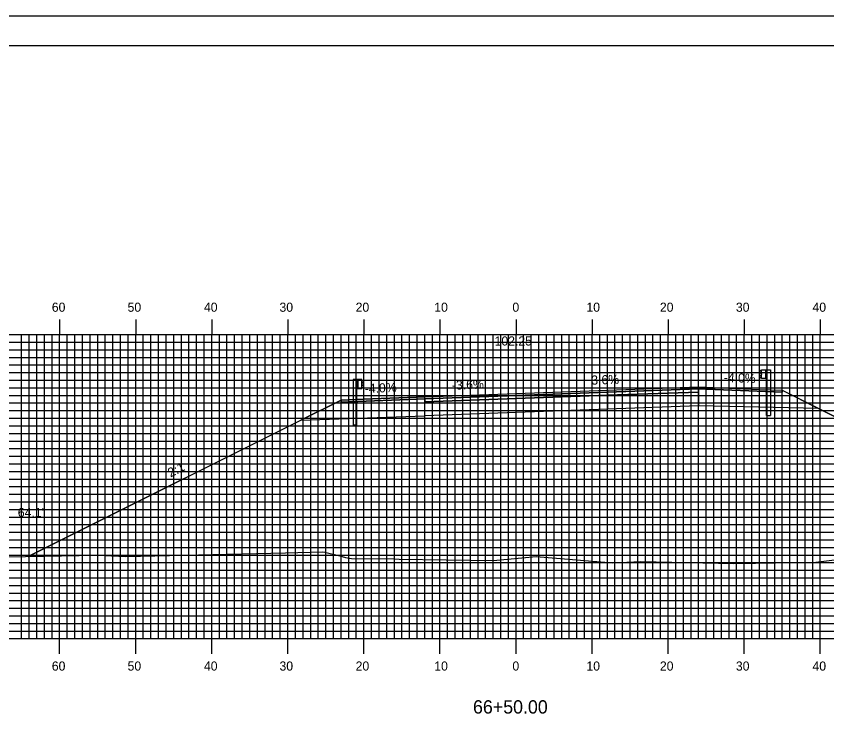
# Model space of a CAD drawing. Extents: x 1759036 to 1759380, y 442591 to 442811.
# Drawn here: x 1759136.4 to 1759243, y 442716.9 to 442810.5 of the extents above; entities that cross this region are included whole.
import ezdxf

# ---------------------------------------------------------------- set-up
doc = ezdxf.new("R2010")
doc.units = 0
for name, color, linetype in [('ANNOTATION', 7, 'Continuous'), ('BORDER', 7, 'Continuous'), ('D_Guardrail_Beam_Lt', 7, 'Continuous'), ('D_Guardrail_Beam_Rt', 7, 'Continuous'), ('D_Roadway_Centerline', 7, 'Continuous'), ('D_Roadway_Centerline_Text', 7, 'Continuous'), ('D_Roadway_Edge_Shoulder', 7, 'Continuous'), ('D_Roadway_Edge_TW', 7, 'Continuous'), ('D_Roadway_Pavement', 7, 'Continuous'), ('D_Roadway_SlopeLines', 7, 'Continuous'), ('D_Roadway_SubGrade', 7, 'Continuous'), ('D_Text_Standard', 7, 'Continuous'), ('H_V ANNOTATION', 7, 'Continuous'), ('MAJOR', 7, 'Continuous'), ('MINOR', 7, 'Continuous'), ('PLOT BOUNDARY', 7, 'Continuous'), ('S_Roadway_Centerline', 7, 'Continuous')]:
    doc.layers.add(name, color=color, linetype=linetype)

msp = doc.modelspace()

# ---------------------------------------------------------------- linework, layer by layer
at = {"layer": 'BORDER'}
msp.add_lwpolyline([(1759052.56, 442596.67), (1759372.56, 442596.67), (1759372.56, 442806.67), (1759052.56, 442806.67)], close=True, dxfattribs=at)
at = {"layer": 'D_Guardrail_Beam_Lt'}
for p, q in [((1759180.73, 442762.75), (1759180.73, 442756.75)), ((1759181.2, 442762.75), (1759180.73, 442762.75)), ((1759181.89, 442762.75), (1759181.2, 442762.75)), ((1759181.2, 442762.75), (1759181.2, 442761.58)), ((1759181.27, 442762.75), (1759181.27, 442761.58)), ((1759181.37, 442762.75), (1759181.37, 442761.58)), ((1759181.89, 442761.58), (1759181.89, 442762.75)), ((1759181.89, 442762.66), (1759181.96, 442762.65)), ((1759181.9, 442762.2), (1759181.9, 442762.13)), ((1759182.12, 442762.4), (1759181.93, 442762.26)), ((1759181.93, 442762.06), (1759182.12, 442761.93)), ((1759181.98, 442762.64), (1759182.12, 442762.54)), ((1759181.2, 442761.58), (1759181.89, 442761.58)), ((1759181.22, 442756.75), (1759181.22, 442761.58)), ((1759181.96, 442761.68), (1759181.89, 442761.66)), ((1759182.12, 442761.78), (1759181.98, 442761.68)), ((1759181.22, 442756.75), (1759180.73, 442756.75))]:
    msp.add_line(p, q, dxfattribs=at)
for centre, major_axis, start_param, end_param in [((1759181.97, 442762.2), (-0.0789, 0), 5.323254, 6.283185), ((1759181.97, 442762.13), (-0.0789, 0), 6.283185, 7.243116), ((1759181.96, 442762.61), (0.0417, 0), 0.959931, 1.376053), ((1759182.07, 442762.47), (0.0877, 0), 5.323254, 7.243116), ((1759182.07, 442761.86), (0.0877, 0), 5.323254, 7.243116), ((1759181.96, 442761.72), (0.0417, 0), 4.907132, 5.323254)]:
    msp.add_ellipse(centre, major_axis=major_axis, ratio=0.995501, start_param=start_param, end_param=end_param, dxfattribs=at)
at = {"layer": 'D_Guardrail_Beam_Rt'}
for p, q in [((1759234.43, 442764.04), (1759235.12, 442764.04)), ((1759234.43, 442762.88), (1759234.43, 442764.04)), ((1759234.95, 442764.04), (1759234.95, 442762.88)), ((1759235.06, 442764.04), (1759235.06, 442762.88)), ((1759235.12, 442764.04), (1759235.59, 442764.04)), ((1759235.12, 442764.04), (1759235.12, 442762.88)), ((1759235.59, 442764.04), (1759235.59, 442758.04)), ((1759234.34, 442763.94), (1759234.2, 442763.84)), ((1759234.2, 442763.69), (1759234.39, 442763.56)), ((1759234.39, 442763.36), (1759234.2, 442763.22)), ((1759234.2, 442763.08), (1759234.34, 442762.98)), ((1759234.43, 442763.96), (1759234.36, 442763.94)), ((1759234.36, 442762.97), (1759234.43, 442762.96)), ((1759234.43, 442763.49), (1759234.43, 442763.42)), ((1759235.12, 442762.88), (1759234.43, 442762.88)), ((1759235.1, 442758.04), (1759235.1, 442762.88)), ((1759235.1, 442758.04), (1759235.59, 442758.04))]:
    msp.add_line(p, q, dxfattribs=at)
for centre, major_axis, start_param, end_param in [((1759234.25, 442763.77), (-0.0877, 0), 5.323254, 7.243116), ((1759234.25, 442763.15), (-0.0877, 0), 5.323254, 7.243116), ((1759234.37, 442763.9), (-0.0417, 0), 4.907132, 5.323254), ((1759234.37, 442763.01), (-0.0417, 0), 0.959931, 1.376053), ((1759234.35, 442763.49), (0.0789, 0), 0, 0.959931), ((1759234.35, 442763.42), (0.0789, 0), 5.323254, 6.283185)]:
    msp.add_ellipse(centre, major_axis=major_axis, ratio=0.995501, start_param=start_param, end_param=end_param, dxfattribs=at)
at = {"layer": 'D_Roadway_Centerline'}
msp.add_lwpolyline([(1759138.03, 442739.48), (1759173.87, 442757.4), (1759179.16, 442760.04), (1759182.16, 442760.16), (1759190.16, 442760.48), (1759202.16, 442760.91), (1759214.16, 442761.35), (1759226.16, 442761.78), (1759234.16, 442761.46), (1759237.16, 442761.34), (1759241.91, 442758.96), (1759280.16, 442739.84)], dxfattribs=at)
at = {"layer": 'D_Roadway_Edge_Shoulder'}
for points in [[(1759226.16, 442761.78), (1759234.16, 442761.46), (1759234.16, 442761.46), (1759237.16, 442761.34), (1759237.16, 442761.09), (1759226.16, 442761.53)], [(1759190.16, 442760.48), (1759182.16, 442760.16), (1759182.16, 442760.16), (1759179.16, 442760.04), (1759179.16, 442759.79), (1759190.16, 442760.23)]]:
    msp.add_lwpolyline(points, close=True, dxfattribs=at)
at = {"layer": 'D_Roadway_Edge_TW'}
for points in [[(1759190.16, 442760.23), (1759190.16, 442760.48), (1759202.16, 442760.91), (1759214.16, 442761.35), (1759214.16, 442761.1), (1759202.16, 442760.66)], [(1759214.16, 442761.35), (1759226.16, 442761.78), (1759226.16, 442761.53), (1759214.16, 442761.1)]]:
    msp.add_lwpolyline(points, close=True, dxfattribs=at)
at = {"layer": 'D_Roadway_Pavement'}
for points in [[(1759190.16, 442759.82), (1759190.16, 442760.23), (1759202.16, 442760.66), (1759214.16, 442761.1), (1759214.16, 442760.68), (1759202.16, 442760.25)], [(1759214.16, 442761.1), (1759226.16, 442761.53), (1759226.16, 442761.11), (1759214.16, 442760.68)]]:
    msp.add_lwpolyline(points, close=True, dxfattribs=at)
for points in [[(1759226.16, 442761.53), (1759226.16, 442761.11)], [(1759226.16, 442761.53), (1759226.16, 442761.11)], [(1759190.16, 442760.23), (1759190.16, 442759.82)]]:
    msp.add_lwpolyline(points, dxfattribs=at)
at = {"layer": 'D_Roadway_SlopeLines'}
for points in [[(1759237.16, 442761.34), (1759280.16, 442739.84)], [(1759179.16, 442760.04), (1759138.03, 442739.48)]]:
    msp.add_lwpolyline(points, dxfattribs=at)
at = {"layer": 'D_Roadway_SubGrade'}
for points in [[(1759214.16, 442760.68), (1759226.16, 442761.11), (1759226.16, 442759.28), (1759214.16, 442758.85)], [(1759226.16, 442761.11), (1759226.16, 442761.53), (1759237.16, 442761.09), (1759237.16, 442761.34), (1759241.91, 442758.96), (1759226.16, 442759.28)], [(1759190.16, 442759.82), (1759190.16, 442760.23), (1759179.16, 442759.79), (1759179.16, 442760.04), (1759173.87, 442757.4), (1759190.16, 442757.98)], [(1759190.16, 442757.98), (1759190.16, 442759.82), (1759202.16, 442760.25), (1759214.16, 442760.68), (1759214.16, 442758.85), (1759202.16, 442758.41)]]:
    msp.add_lwpolyline(points, close=True, dxfattribs=at)
at = {"layer": 'MAJOR'}
for p, q in [((1759142.16, 442770.67), (1759142.16, 442768.67)), ((1759152.16, 442770.67), (1759152.16, 442768.67)), ((1759162.16, 442770.67), (1759162.16, 442768.67)), ((1759172.16, 442770.67), (1759172.16, 442768.67)), ((1759182.16, 442770.67), (1759182.16, 442768.67)), ((1759192.16, 442770.67), (1759192.16, 442768.67)), ((1759202.16, 442770.67), (1759202.16, 442768.67)), ((1759212.16, 442770.67), (1759212.16, 442768.67)), ((1759222.16, 442770.67), (1759222.16, 442768.67)), ((1759232.16, 442770.67), (1759232.16, 442768.67)), ((1759242.16, 442770.67), (1759242.16, 442768.67)), ((1759062.16, 442768.67), (1759342.16, 442768.67)), ((1759062.16, 442768.67), (1759342.16, 442768.67)), ((1759142.16, 442728.67), (1759142.16, 442768.67)), ((1759152.16, 442728.67), (1759152.16, 442768.67)), ((1759162.16, 442728.67), (1759162.16, 442768.67)), ((1759172.16, 442728.67), (1759172.16, 442768.67)), ((1759182.16, 442728.67), (1759182.16, 442768.67)), ((1759192.16, 442728.67), (1759192.16, 442768.67)), ((1759202.16, 442728.67), (1759202.16, 442768.67)), ((1759212.16, 442728.67), (1759212.16, 442768.67)), ((1759222.16, 442728.67), (1759222.16, 442768.67)), ((1759232.16, 442728.67), (1759232.16, 442768.67)), ((1759242.16, 442728.67), (1759242.16, 442768.67)), ((1759062.16, 442763.67), (1759342.16, 442763.67)), ((1759062.16, 442758.67), (1759342.16, 442758.67)), ((1759062.16, 442753.67), (1759342.16, 442753.67)), ((1759062.16, 442748.67), (1759342.16, 442748.67)), ((1759062.16, 442743.67), (1759342.16, 442743.67)), ((1759062.16, 442738.67), (1759342.16, 442738.67)), ((1759062.16, 442733.67), (1759342.16, 442733.67)), ((1759062.16, 442728.67), (1759342.16, 442728.67)), ((1759062.16, 442728.67), (1759342.16, 442728.67)), ((1759142.16, 442726.66), (1759142.16, 442728.67)), ((1759152.16, 442726.66), (1759152.16, 442728.67)), ((1759162.16, 442726.66), (1759162.16, 442728.67)), ((1759172.16, 442726.66), (1759172.16, 442728.67)), ((1759182.16, 442726.66), (1759182.16, 442728.67)), ((1759192.16, 442726.66), (1759192.16, 442728.67)), ((1759202.16, 442726.66), (1759202.16, 442728.67)), ((1759212.16, 442726.66), (1759212.16, 442728.67)), ((1759222.16, 442726.66), (1759222.16, 442728.67)), ((1759232.16, 442726.66), (1759232.16, 442728.67)), ((1759242.16, 442726.66), (1759242.16, 442728.67))]:
    msp.add_line(p, q, dxfattribs=at)
at = {"layer": 'MINOR'}
for p, q in [((1759137.16, 442728.67), (1759137.16, 442768.67)), ((1759138.16, 442728.67), (1759138.16, 442768.67)), ((1759139.16, 442728.67), (1759139.16, 442768.67)), ((1759140.16, 442728.67), (1759140.16, 442768.67)), ((1759141.16, 442728.67), (1759141.16, 442768.67)), ((1759143.16, 442728.67), (1759143.16, 442768.67)), ((1759144.16, 442728.67), (1759144.16, 442768.67)), ((1759145.16, 442728.67), (1759145.16, 442768.67)), ((1759146.16, 442728.67), (1759146.16, 442768.67)), ((1759147.16, 442728.67), (1759147.16, 442768.67)), ((1759148.16, 442728.67), (1759148.16, 442768.67)), ((1759149.16, 442728.67), (1759149.16, 442768.67)), ((1759150.16, 442728.67), (1759150.16, 442768.67)), ((1759151.16, 442728.67), (1759151.16, 442768.67)), ((1759153.16, 442728.67), (1759153.16, 442768.67)), ((1759154.16, 442728.67), (1759154.16, 442768.67)), ((1759155.16, 442728.67), (1759155.16, 442768.67)), ((1759156.16, 442728.67), (1759156.16, 442768.67)), ((1759157.16, 442728.67), (1759157.16, 442768.67)), ((1759158.16, 442728.67), (1759158.16, 442768.67)), ((1759159.16, 442728.67), (1759159.16, 442768.67)), ((1759160.16, 442728.67), (1759160.16, 442768.67)), ((1759161.16, 442728.67), (1759161.16, 442768.67)), ((1759163.16, 442728.67), (1759163.16, 442768.67)), ((1759164.16, 442728.67), (1759164.16, 442768.67)), ((1759165.16, 442728.67), (1759165.16, 442768.67)), ((1759166.16, 442728.67), (1759166.16, 442768.67)), ((1759167.16, 442728.67), (1759167.16, 442768.67)), ((1759168.16, 442728.67), (1759168.16, 442768.67)), ((1759169.16, 442728.67), (1759169.16, 442768.67)), ((1759170.16, 442728.67), (1759170.16, 442768.67)), ((1759171.16, 442728.67), (1759171.16, 442768.67)), ((1759173.16, 442728.67), (1759173.16, 442768.67)), ((1759174.16, 442728.67), (1759174.16, 442768.67)), ((1759175.16, 442728.67), (1759175.16, 442768.67)), ((1759176.16, 442728.67), (1759176.16, 442768.67)), ((1759177.16, 442728.67), (1759177.16, 442768.67)), ((1759178.16, 442728.67), (1759178.16, 442768.67)), ((1759179.16, 442728.67), (1759179.16, 442768.67)), ((1759180.16, 442728.67), (1759180.16, 442768.67)), ((1759181.16, 442728.67), (1759181.16, 442768.67)), ((1759183.16, 442728.67), (1759183.16, 442768.67)), ((1759184.16, 442728.67), (1759184.16, 442768.67)), ((1759185.16, 442728.67), (1759185.16, 442768.67)), ((1759186.16, 442728.67), (1759186.16, 442768.67)), ((1759187.16, 442728.67), (1759187.16, 442768.67)), ((1759188.16, 442728.67), (1759188.16, 442768.67)), ((1759189.16, 442728.67), (1759189.16, 442768.67)), ((1759190.16, 442728.67), (1759190.16, 442768.67)), ((1759191.16, 442728.67), (1759191.16, 442768.67)), ((1759193.16, 442728.67), (1759193.16, 442768.67)), ((1759194.16, 442728.67), (1759194.16, 442768.67)), ((1759195.16, 442728.67), (1759195.16, 442768.67)), ((1759196.16, 442728.67), (1759196.16, 442768.67)), ((1759197.16, 442728.67), (1759197.16, 442768.67)), ((1759198.16, 442728.67), (1759198.16, 442768.67)), ((1759199.16, 442728.67), (1759199.16, 442768.67)), ((1759200.16, 442728.67), (1759200.16, 442768.67)), ((1759201.16, 442728.67), (1759201.16, 442768.67)), ((1759203.16, 442728.67), (1759203.16, 442768.67)), ((1759204.16, 442728.67), (1759204.16, 442768.67)), ((1759205.16, 442728.67), (1759205.16, 442768.67)), ((1759206.16, 442728.67), (1759206.16, 442768.67)), ((1759207.16, 442728.67), (1759207.16, 442768.67)), ((1759208.16, 442728.67), (1759208.16, 442768.67)), ((1759209.16, 442728.67), (1759209.16, 442768.67)), ((1759210.16, 442728.67), (1759210.16, 442768.67)), ((1759211.16, 442728.67), (1759211.16, 442768.67)), ((1759213.16, 442728.67), (1759213.16, 442768.67)), ((1759214.16, 442728.67), (1759214.16, 442768.67)), ((1759215.16, 442728.67), (1759215.16, 442768.67)), ((1759216.16, 442728.67), (1759216.16, 442768.67)), ((1759217.16, 442728.67), (1759217.16, 442768.67)), ((1759218.16, 442728.67), (1759218.16, 442768.67)), ((1759219.16, 442728.67), (1759219.16, 442768.67)), ((1759220.16, 442728.67), (1759220.16, 442768.67)), ((1759221.16, 442728.67), (1759221.16, 442768.67)), ((1759223.16, 442728.67), (1759223.16, 442768.67)), ((1759224.16, 442728.67), (1759224.16, 442768.67)), ((1759225.16, 442728.67), (1759225.16, 442768.67)), ((1759226.16, 442728.67), (1759226.16, 442768.67)), ((1759227.16, 442728.67), (1759227.16, 442768.67)), ((1759228.16, 442728.67), (1759228.16, 442768.67)), ((1759229.16, 442728.67), (1759229.16, 442768.67)), ((1759230.16, 442728.67), (1759230.16, 442768.67)), ((1759231.16, 442728.67), (1759231.16, 442768.67)), ((1759233.16, 442728.67), (1759233.16, 442768.67)), ((1759234.16, 442728.67), (1759234.16, 442768.67)), ((1759235.16, 442728.67), (1759235.16, 442768.67)), ((1759236.16, 442728.67), (1759236.16, 442768.67)), ((1759237.16, 442728.67), (1759237.16, 442768.67)), ((1759238.16, 442728.67), (1759238.16, 442768.67)), ((1759239.16, 442728.67), (1759239.16, 442768.67)), ((1759240.16, 442728.67), (1759240.16, 442768.67)), ((1759241.16, 442728.67), (1759241.16, 442768.67)), ((1759062.16, 442767.67), (1759342.16, 442767.67)), ((1759062.16, 442766.67), (1759342.16, 442766.67)), ((1759062.16, 442765.67), (1759342.16, 442765.67)), ((1759062.16, 442764.67), (1759342.16, 442764.67)), ((1759062.16, 442762.67), (1759342.16, 442762.67)), ((1759062.16, 442761.67), (1759342.16, 442761.67)), ((1759062.16, 442760.67), (1759342.16, 442760.67)), ((1759062.16, 442759.67), (1759342.16, 442759.67)), ((1759062.16, 442757.67), (1759342.16, 442757.67)), ((1759062.16, 442756.67), (1759342.16, 442756.67)), ((1759062.16, 442755.67), (1759342.16, 442755.67)), ((1759062.16, 442754.67), (1759342.16, 442754.67)), ((1759062.16, 442752.67), (1759342.16, 442752.67)), ((1759062.16, 442751.67), (1759342.16, 442751.67)), ((1759062.16, 442750.67), (1759342.16, 442750.67)), ((1759062.16, 442749.67), (1759342.16, 442749.67)), ((1759062.16, 442747.67), (1759342.16, 442747.67)), ((1759062.16, 442746.67), (1759342.16, 442746.67)), ((1759062.16, 442745.67), (1759342.16, 442745.67)), ((1759062.16, 442744.67), (1759342.16, 442744.67)), ((1759062.16, 442742.67), (1759342.16, 442742.67)), ((1759062.16, 442741.67), (1759342.16, 442741.67)), ((1759062.16, 442740.67), (1759342.16, 442740.67)), ((1759062.16, 442739.67), (1759342.16, 442739.67)), ((1759062.16, 442737.67), (1759342.16, 442737.67)), ((1759062.16, 442736.67), (1759342.16, 442736.67)), ((1759062.16, 442735.67), (1759342.16, 442735.67)), ((1759062.16, 442734.67), (1759342.16, 442734.67)), ((1759062.16, 442732.67), (1759342.16, 442732.67)), ((1759062.16, 442731.67), (1759342.16, 442731.67)), ((1759062.16, 442730.67), (1759342.16, 442730.67)), ((1759062.16, 442729.67), (1759342.16, 442729.67))]:
    msp.add_line(p, q, dxfattribs=at)
at = {"layer": 'PLOT BOUNDARY'}
msp.add_lwpolyline([(1759036.37, 442590.55), (1759376.37, 442590.55), (1759376.37, 442810.55), (1759036.37, 442810.55)], close=True, dxfattribs=at)
at = {"layer": 'S_Roadway_Centerline'}
msp.add_lwpolyline([(1759111.78, 442739.01), (1759147.1, 442739.64), (1759150.84, 442739.47), (1759171.83, 442739.97), (1759176.76, 442740.11), (1759177.01, 442740.03), (1759178.8, 442739.63), (1759178.85, 442739.63), (1759179.73, 442739.33), (1759180.53, 442739.22), (1759186.11, 442739.17), (1759186.79, 442739.14), (1759199.14, 442738.94), (1759204.79, 442739.46), (1759214.87, 442738.63), (1759218.57, 442738.8), (1759230.81, 442738.54), (1759233.64, 442738.6), (1759241.56, 442738.74), (1759249.63, 442739.75)], dxfattribs=at)

# ---------------------------------------------------------------- texts
at = {"layer": 'ANNOTATION'}
for s, rotation, p in [('3.6%', 2.0618, (1759212.07, 442762.07)), ('-4.0%', 357.7094, (1759229.45, 442762.45)), ('-4.0%', 2.2906, (1759182.29, 442760.97)), ('-3.6%', 2.0618, (1759193.75, 442761.41)), ('2:1', 26.5651, (1759156.74, 442749.87))]:
    msp.add_text(s, height=1.2, rotation=rotation, dxfattribs=at).set_placement(p)
at = {"layer": 'D_Roadway_Centerline'}
for s in ['C', 'L']:
    msp.add_text(s, height=0.0146, dxfattribs=at).set_placement((1759202.16, 442760.91))
at = {"layer": 'D_Roadway_Centerline_Text'}
msp.add_text('102.25', height=1.2, dxfattribs=at).set_placement((1759199.34, 442767.23))
at = {"layer": 'D_Text_Standard'}
msp.add_text("64.1'", height=1.2, dxfattribs=at).set_placement((1759136.66, 442744.67))
at = {"layer": 'H_V ANNOTATION'}
for s, height, p in [('60', 1.2, (1759141.13, 442771.67)), ('50', 1.2, (1759151.09, 442771.67)), ('40', 1.2, (1759161.13, 442771.67)), ('30', 1.2, (1759171.06, 442771.67)), ('20', 1.2, (1759181.07, 442771.67)), ('10', 1.2, (1759191.41, 442771.67)), ('0', 1.2, (1759201.68, 442771.67)), ('10', 1.2, (1759211.41, 442771.67)), ('20', 1.2, (1759221.07, 442771.67)), ('30', 1.2, (1759231.06, 442771.67)), ('40', 1.2, (1759241.13, 442771.67)), ('60', 1.2, (1759141.13, 442724.47)), ('50', 1.2, (1759151.09, 442724.47)), ('40', 1.2, (1759161.13, 442724.47)), ('30', 1.2, (1759171.06, 442724.47)), ('20', 1.2, (1759181.07, 442724.47)), ('10', 1.2, (1759191.41, 442724.47)), ('0', 1.2, (1759201.68, 442724.47)), ('10', 1.2, (1759211.41, 442724.47)), ('20', 1.2, (1759221.07, 442724.47)), ('30', 1.2, (1759231.06, 442724.47)), ('40', 1.2, (1759241.13, 442724.47)), ('66+50.00', 1.75, (1759196.5, 442718.82))]:
    msp.add_text(s, height=height, dxfattribs=at).set_placement(p)

doc.saveas('drawing.dxf')
